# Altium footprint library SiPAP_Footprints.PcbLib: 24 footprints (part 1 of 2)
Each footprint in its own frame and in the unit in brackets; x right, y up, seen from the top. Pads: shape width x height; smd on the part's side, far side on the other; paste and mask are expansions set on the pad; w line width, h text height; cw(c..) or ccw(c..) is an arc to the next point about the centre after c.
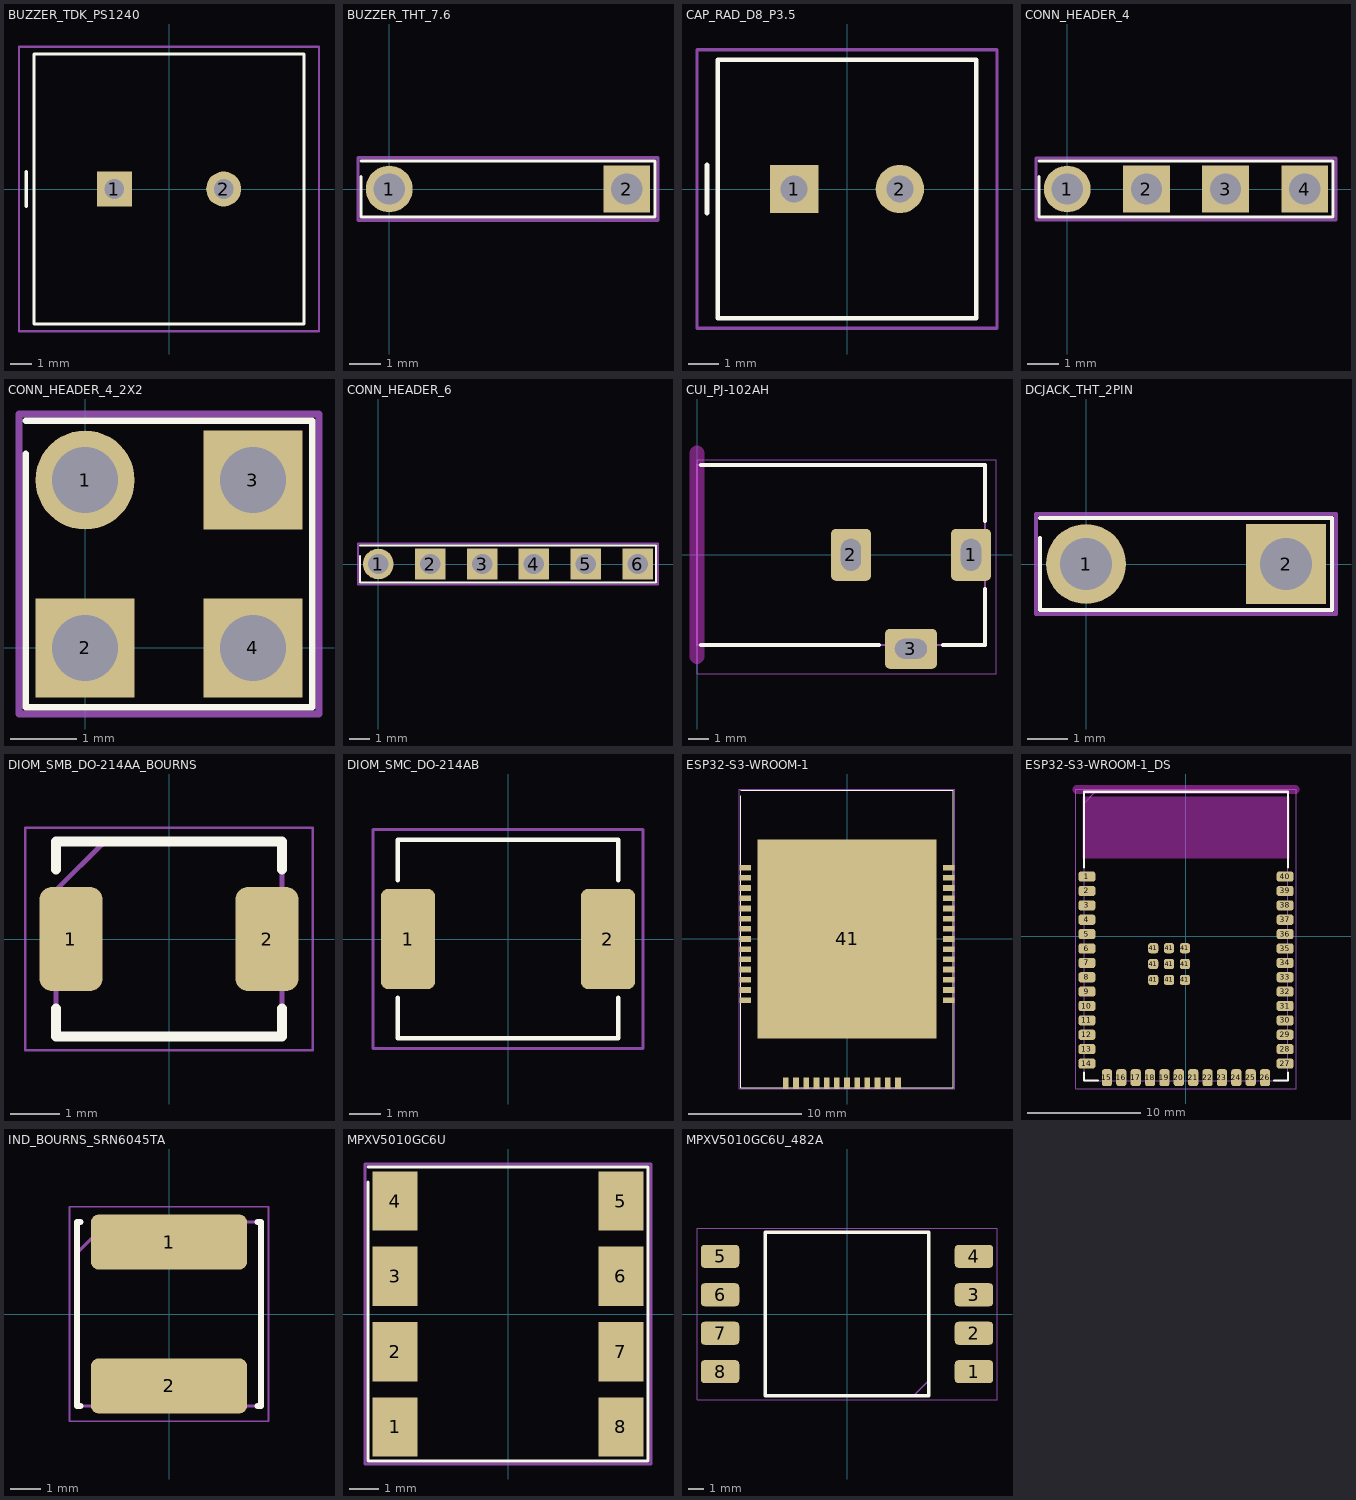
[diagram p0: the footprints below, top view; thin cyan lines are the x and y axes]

## BUZZER_TDK_PS1240 [mil] "TDK PS1240P02BT piezo buzzer (TDK PS series p2-3: dia 12.2, H 6.5, pitch 5.0, pin 0.65). Hole 0.9 mm."
pads (2):
  rect 63x63 hole 35.4: 1(-98.42,0)
  round 63 hole 35.4: 2(98.42,0)
Top Overlay:
  lines w6: -257,-31.5 -257,31.5 ; -243,-243 -243,243 243,243 243,-243 -243,-243
Mechanical 1:
  lines w4: -270,-256 -270,256 270,256 270,-256 -270,-256
3D body: height 255.91, standoff 0, extent -240.16,-240.16 240.16,240.16

## BUZZER_THT_7.6 [mm] "Generic THT piezo buzzer, 7.6mm pin pitch"
pads (2):
  round 1.5 smd: 1(0,0)
  rect 1.5x1.5 smd: 2(7.6,0)
Top Overlay:
  lines w0.1: -0.9,0.4 -0.9,-0.9 8.5,-0.9 8.5,0.9 -0.9,0.9
Mechanical 15:
  lines w0.1: -1,-1 8.6,-1 8.6,1 -1,1 -1,-1
3D body: height 9.5, standoff 0, extent -2.2,-6 9.8,6

## CAP_RAD_D8_P3.5 [mil] "Radial aluminium electrolytic D8 mm, lead pitch 3.5 mm, lead 0.6 mm (Panasonic EEU-FC1E221, FC-A series p6). Pad 1 (square) = +. Hole 0.9 mm."
pads (2):
  rect 63x63 hole 35.4: 1(-68.9,0)
  round 63 hole 35.4: 2(68.9,0)
Top Overlay:
  lines w6: -182.5,-31.5 -182.5,31.5 ; -168.5,-168.5 168.5,-168.5 168.5,168.5 -168.5,168.5 -168.5,-168.5
Mechanical 1:
  lines w4: -195.5,-181.5 195.5,-181.5 195.5,181.5 -195.5,181.5 -195.5,-181.5
3D body: height 452.76, standoff 0, extent -157.48,-157.48 157.48,157.48

## CONN_HEADER_4 [mm] "4-pin THT header, single row, 2.54mm pitch (OLED / buck module)"
pads (4):
  round 1.5 smd: 1(0,0)
  rect 1.5x1.5 smd: 2(2.54,0) 3(5.08,0) 4(7.62,0)
Top Overlay:
  lines w0.1: -0.9,0.4 -0.9,-0.9 8.52,-0.9 8.52,0.9 -0.9,0.9
Mechanical 15:
  lines w0.1: -1,-1 -1,1 8.62,1 8.62,-1 -1,-1
3D body: height 2.5, standoff 0, extent -1.27,-1.27 8.89,1.27
3D body: height 8.5, standoff 2.5, extent -0.5,-0.5 8.12,0.5

## CONN_HEADER_4_2X2 [mm] "4-pin THT header, 2x2, 2.54mm pitch (blower cable connector)"
pads (4):
  round 1.5 smd: 1(0,2.54)
  rect 1.5x1.5 smd: 2(0,0) 3(2.54,2.54) 4(2.54,0)
Top Overlay:
  lines w0.1: -0.9,2.94 -0.9,-0.9 3.44,-0.9 3.44,3.44 -0.9,3.44
Mechanical 15:
  lines w0.1: -1,-1 -1,3.54 3.54,3.54 3.54,-1 -1,-1
3D body: height 2.5, standoff 0, extent -1.27,-1.27 3.81,3.81
3D body: height 8.5, standoff 2.5, extent -0.5,-0.5 3.04,3.04

## CONN_HEADER_6 [mm] "6-pin THT header 2.54mm pitch, single row (for SFM3300-D cable connector)"
pads (6):
  round 1.5 smd: 1(0,0)
  rect 1.5x1.5 smd: 2(2.54,0) 3(5.08,0) 4(7.62,0) 5(10.16,0) 6(12.7,0)
Top Overlay:
  lines w0.1: -0.9,0.4 -0.9,-0.9 13.6,-0.9 13.6,0.9 -0.9,0.9
Mechanical 15:
  lines w0.1: -1,-1 -1,1 13.7,1 13.7,-1 -1,-1
3D body: height 2.5, standoff 0, extent -1.27,-1.27 13.97,1.27
3D body: height 8.5, standoff 2.5, extent -0.5,-0.5 13.2,0.5

## CUI_PJ-102AH [mm] "Custom, 3 pads; custom lands, density N (nominal); from Same Sky PJ-102AH datasheet (09/12/2024), Recommended PCB Layout Top View, p. 2; Same Sky PJ-102AH DC jack, 2.0 mm pin, 5 A. Layout p2. Origin = plug-entry face on jack axis (place at board edge). Pin1 centre (+), pin2 sleeve, pin3 switch. Slots 1.0x1.6."
height 11
pads (3):
  rrect25% 2x2.6 hole 1 slot 1.6 at 90 deg: 1(13.7,0) 2(7.7,0)
  rrect25% 2.6x2 hole 1 slot 1.6 at 0 deg: 3(10.7,-4.7)
Top Overlay:
  lines w0.2: 0.2,-4.5 9.1,-4.5 ; 0.2,4.5 14.4,4.5 14.4,1.7 ; 12.3,-4.5 14.4,-4.5 14.4,-1.7
Keep-Out Layer:
  lines w0.762: 0,-5.08 0,5.08
Mechanical 13:
  lines w0.1: 0,-4.5 14.4,-4.5 14.4,4.5 0,4.5 0,-4.5
  text ".Designator" at -5.075,-0.5 h1
Mechanical 15:
  lines w0.05: 0,-5.95 14.95,-5.95 14.95,4.75 0,4.75 0,-5.95
3D body: height 11, standoff 0, extent 0,-4.5 14.4,4.5

## DCJACK_THT_2PIN [mm] "Generic 2-pin THT DC barrel jack footprint, 5mm pitch"
pads (2):
  round 2 smd: 1(0,0)
  rect 2x2 smd: 2(5,0)
Top Overlay:
  lines w0.1: -1.15,0.65 -1.15,-1.15 6.15,-1.15 6.15,1.15 -1.15,1.15
Mechanical 15:
  lines w0.1: -1.25,-1.25 -1.25,1.25 6.25,1.25 6.25,-1.25 -1.25,-1.25
3D body: height 11, standoff 0, extent -2,-7 7,7

## DIOM_SMB_DO-214AA_BOURNS [mm] "Custom, 2 pads; custom lands, density N (nominal); from Bourns SMBJ Series TVS datasheet, Recommended Footprint SMB (DO-214AA), p. 3; Bourns SMB (DO-214AA) recommended footprint p3. Pad1 = cathode (band), pad2 = anode."
height 2.44
pads (2):
  rrect39% 1.27x2.1 smd: 1(-1.98,0) 2(1.98,0)
Top Overlay:
  lines w0.2: -2.285,-1.4 -2.285,-1.97 2.285,-1.97 2.285,-1.4 ; -2.285,1.4 -2.285,1.97 2.285,1.97 2.285,1.4
Mechanical 13:
  lines w0.1: -2.285,-1.97 -2.285,0.985 -1.3,1.97 2.285,1.97 2.285,-1.97 -2.285,-1.97
  text ".Designator" at -2.055,-0.202 h0.41
Mechanical 15:
  lines w0.05: -2.9,-2.25 -2.9,2.25 2.9,2.25 2.9,-2.25 -2.9,-2.25
3D body: height 2.44, standoff 0, extent -2.3,-1.95 2.3,1.95

## DIOM_SMC_DO-214AB [mil] "DO-214AB (SMC) diode, Vishay SMC mounting pad layout (pad 3.20 x 1.72mm, gap 4.69mm, 8.13mm overall). Pad1=A, Pad2=K (cathode band at pad 2)"
pads (2):
  rrect25% 68x126 smd: 1(-126,0) 2(126,0)
Top Overlay:
  lines w6: -139,-74 -139,-125 139,-125 139,-74 ; -139,74 -139,125 139,125 139,74
Mechanical 1:
  lines w4: -170,-138 -170,138 170,138 170,-138 -170,-138
3D body: height 103.15, standoff 0, extent -137.8,-118.11 137.8,118.11

## ESP32-S3-WROOM-1 [mm] "Espressif ESP32-S3-WROOM-1 castellated module, 18x25.5mm body, 0.9mm pitch (datasheet Fig 10-1, v1.8)"
pads (41):
  rect 1x0.5 smd: 1(-9,6.3) 2(-9,5.4) 3(-9,4.5) 4(-9,3.6) 5(-9,2.7) 6(-9,1.8) 7(-9,0.9) 8(-9,0) 9(-9,-0.9) 10(-9,-1.8) 11(-9,-2.7) 12(-9,-3.6) 13(-9,-4.5) 14(-9,-5.4) 27(9,-5.4) 28(9,-4.5) 29(9,-3.6) 30(9,-2.7) 31(9,-1.8) 32(9,-0.9) 33(9,0) 34(9,0.9) 35(9,1.8) 36(9,2.7) 37(9,3.6) 38(9,4.5) 39(9,5.4) 40(9,6.3)
  rect 0.5x1 smd: 15(-5.4,-12.75) 16(-4.5,-12.75) 17(-3.6,-12.75) 18(-2.7,-12.75) 19(-1.8,-12.75) 20(-0.9,-12.75) 21(0,-12.75) 22(0.9,-12.75) 23(1.8,-12.75) 24(2.7,-12.75) 25(3.6,-12.75) 26(4.5,-12.75)
  rect 15.8x17.6 smd: 41(0,0)
Top Overlay:
  lines w0.1: -9.4,12.65 -9.4,-13.15 9.4,-13.15 9.4,13.15 -9.4,13.15
Mechanical 15:
  lines w0.1: -9.5,-13.25 -9.5,13.25 9.5,13.25 9.5,-13.25 -9.5,-13.25

## ESP32-S3-WROOM-1_DS [mm] "Custom, 41 pads; custom lands, density N (nominal); from ESP32-S3-WROOM-1 & WROOM-1U Datasheet, v1.8, Figure 11-1 Recommended PCB Land Pattern, p. 45; Espressif datasheet v1.8 Fig 11-1. Origin = module centre. Antenna area = top 6 mm: keep copper out."
height 3.1
pads (49):
  rrect50% 1.5x0.9 smd: 1(-8.75,5.26) 2(-8.75,3.99) 3(-8.75,2.72) 4(-8.75,1.45) 5(-8.75,0.18) 6(-8.75,-1.09) 7(-8.75,-2.36) 8(-8.75,-3.63) 9(-8.75,-4.9) 10(-8.75,-6.17) 11(-8.75,-7.44) 12(-8.75,-8.71) 13(-8.75,-9.98) 14(-8.75,-11.25) 27(8.75,-11.25) 28(8.75,-9.98) 29(8.75,-8.71) 30(8.75,-7.44) 31(8.75,-6.17) 32(8.75,-4.9) 33(8.75,-3.63) 34(8.75,-2.36) 35(8.75,-1.09) 36(8.75,0.18) 37(8.75,1.45) 38(8.75,2.72) 39(8.75,3.99) 40(8.75,5.26)
  rrect50% 0.9x1.5 smd: 15(-6.985,-12.5) 16(-5.715,-12.5) 17(-4.445,-12.5) 18(-3.175,-12.5) 19(-1.905,-12.5) 20(-0.635,-12.5) 21(0.635,-12.5) 22(1.905,-12.5) 23(3.175,-12.5) 24(4.445,-12.5) 25(5.715,-12.5) 26(6.985,-12.5)
  rrect50% 0.9x0.9 smd: 41(-2.9,-3.86) 41(-2.9,-2.46) 41(-2.9,-1.06) 41(-1.5,-3.86) 41(-1.5,-2.46) 41(-1.5,-1.06) 41(-0.1,-3.86) 41(-0.1,-2.46) 41(-0.1,-1.06)
Top Overlay:
  lines w0.2: -9,-12.05 -9,-12.75 -7.785,-12.75 ; -9,6.06 -9,12.75 9,12.75 9,6.06 ; 7.785,-12.75 9,-12.75 9,-12.05
Keep-Out Layer:
  rectangle: -9.144,6.858 9.144,12.319
  lines w0.762: -9.652,12.954 9.652,12.954
Mechanical 13:
  lines w0.1: -9,-12.75 9,-12.75 9,12.75 -8,12.75 -9,11.75 -9,-12.75
  text ".Designator" at -5.075,-0.5 h1
Mechanical 15:
  lines w0.05: -9.75,-13.5 9.75,-13.5 9.75,13 -9.75,13 -9.75,-13.5
3D body: height 0.8, standoff 0, extent -9,-12.75 9,12.75
3D body: height 3.1, standoff 0.8, extent -7.9,-11.7 7.9,5.9

## IND_BOURNS_SRN6045TA [mm] "Custom, 2 pads; custom lands, density N (nominal); from Bourns SRN6045TA Series datasheet, Recommended Layout, p. 1; Bourns SRN6045TA power inductor, recommended layout p1 (6.0x6.0 body, 4.25+/-0.3 tall)."
height 4.55
pads (2):
  rrect28% 5.1x1.8 smd: 1(0,2.35) 2(0,-2.35)
Top Overlay:
  lines w0.2: -2.9,-3 -3,-3 -3,3 -2.9,3 ; 2.9,-3 3,-3 3,3 2.9,3
Mechanical 13:
  lines w0.1: -3,-3 -3,2 -2,3 3,3 3,-3 -3,-3
  text ".Designator" at -2.7,-0.266 h0.53
Mechanical 15:
  lines w0.05: -3.25,-3.5 -3.25,3.5 3.25,3.5 3.25,-3.5 -3.25,-3.5
3D body: height 4.55, standoff 0, extent -3,-3 3,3

## MPXV5010GC6U [mm] "NXP/Motorola Case 482A SOP-8, 2.54mm pitch, 7.62mm row span (Fig 5, Motorola datasheet Rev 8)"
pads (8):
  rect 1.52x2 smd: 1(-3.81,-3.81) 2(-3.81,-1.27) 3(-3.81,1.27) 4(-3.81,3.81) 5(3.81,3.81) 6(3.81,1.27) 7(3.81,-1.27) 8(3.81,-3.81)
Top Overlay:
  lines w0.1: -4.72,4.46 -4.72,-4.96 4.72,-4.96 4.72,4.96 -4.72,4.96
Mechanical 15:
  lines w0.1: -4.82,-5.06 -4.82,5.06 4.82,5.06 4.82,-5.06 -4.82,-5.06

## MPXV5010GC6U_482A [mm] "Custom, 8 pads; custom lands, density N (nominal); from Motorola MPX5010/MPXV5010G Series datasheet (MPX5010/D), 2001, Figure 5 SOP Footprint (Case 482), p. 6; Case 482A land pattern per datasheet Fig 5 p6; pin order per Case 482A top view p7. Height 13.21 max incl. port."
height 13.21
pads (8):
  rrect33% 2.54x1.52 smd: 1(8.38,-3.81) 2(8.38,-1.27) 3(8.38,1.27) 4(8.38,3.81) 5(-8.38,3.81) 6(-8.38,1.27) 7(-8.38,-1.27) 8(-8.38,-3.81)
Top Overlay:
  lines w0.2: -5.395,-5.395 5.395,-5.395 5.395,5.395 -5.395,5.395 -5.395,-5.395
Mechanical 13:
  lines w0.1: -5.395,-5.395 4.395,-5.395 5.395,-4.395 5.395,5.395 -5.395,5.395 -5.395,-5.395
  text ".Designator" at -4.852,-0.478 h0.96
Mechanical 15:
  lines w0.05: -9.9,-5.65 9.9,-5.65 9.9,5.65 -9.9,5.65 -9.9,-5.65
3D body: height 6.99, standoff 0, extent -5.395,-5.395 5.395,5.395
3D body: height 13.21, standoff 6.99, extent -1.585,-1.585 1.585,1.585
3D body: height 1, standoff 0, extent -9.205,-4.35 9.205,4.35

## PCBComponent_1 [mm]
